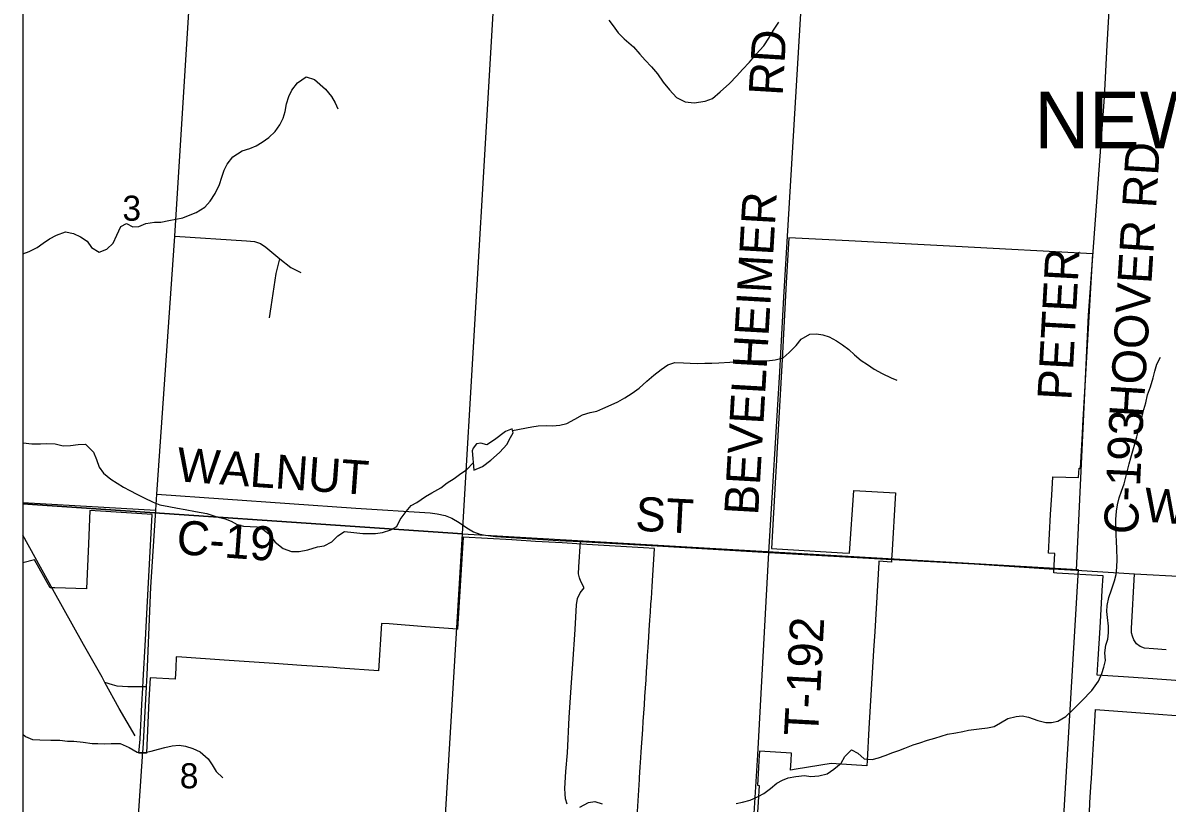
# Model space of a CAD drawing. Extents: x 0 to 91.3, y -0.7 to 22.
# Drawn here: x 2.1 to 4.012, y 19.336 to 20.64 of the extents above; entities that cross this region are included whole.
import ezdxf

# ---------------------------------------------------------------- set-up
doc = ezdxf.new("R2010")
doc.units = 0
for name, color, linetype in [('GM_X_City_Street', 7, 'Continuous'), ('GM_X_Corporation', 7, 'Continuous'), ('GM_X_Corporation_Text', 7, 'Continuous'), ('GM_X_County_Road', 7, 'Continuous'), ('GM_X_County_Road_Text', 7, 'Continuous'), ('GM_X_Minor_Lake', 7, 'Continuous'), ('GM_X_Minor_River', 7, 'Continuous'), ('GM_X_Section_Text', 7, 'Continuous'), ('GM_X_State_Route', 7, 'Continuous'), ('GM_X_Township_Road', 7, 'Continuous'), ('GM_X_Township_Road_Text', 7, 'Continuous'), ('SH_Data', 7, 'Continuous')]:
    doc.layers.add(name, color=color, linetype=linetype)

msp = doc.modelspace()

# ---------------------------------------------------------------- linework, layer by layer
at = {"layer": 'GM_X_City_Street'}
for points in [[(3.0097, 19.3345), (3.0069, 19.3435), (3.0061, 19.352), (3.0058, 19.361), (3.0075, 19.3891), (3.0099, 19.4203), (3.0127, 19.4793), (3.017, 19.5378), (3.0192, 19.5685), (3.0231, 19.6264), (3.0252, 19.6677), (3.0266, 19.6784), (3.031, 19.6876), (3.0381, 19.6961), (3.0324, 19.7065), (3.0299, 19.7128), (3.0285, 19.7196), (3.0288, 19.7311), (3.0318, 19.7734)], [(2.2876, 19.4488), (2.261, 19.4947), (2.2372, 19.5381)]]:
    msp.add_lwpolyline(points, dxfattribs=at)
at = {"layer": 'GM_X_Corporation'}
for points in [[(4.7833, 18.1361), (4.8242, 18.6326), (4.8251, 18.6439), (4.8263, 18.646), (4.8271, 18.6491), (4.8277, 18.656), (4.8336, 18.7529), (4.834, 18.7568), (4.8352, 18.7619), (4.9205, 20.3667), (4.9376, 20.6305), (4.9448, 20.7239), (3.9216, 20.777), (3.4006, 20.8086), (3.3908, 20.8093), (3.2209, 20.8181), (3.0994, 20.8263), (2.3878, 20.8673), (2.1, 20.8844), (2.1, 14.1)], [(4.7833, 18.1361), (4.8242, 18.6326), (4.8251, 18.6439), (4.8263, 18.646), (4.8271, 18.6491), (4.8277, 18.656), (4.8336, 18.7529), (4.834, 18.7568), (4.8352, 18.7619), (4.9205, 20.3667), (4.9376, 20.6305), (4.9448, 20.7239), (3.9216, 20.777), (3.4006, 20.8086), (3.3908, 20.8093), (3.2209, 20.8181), (3.0994, 20.8263), (2.3878, 20.8673), (2.1, 20.8844), (2.1, 15.7138)], [(4.0647, 19.5386), (3.9805, 19.5443), (3.9392, 19.5471), (3.8954, 19.55), (3.897, 19.5771), (3.9, 19.629), (3.9012, 19.6499), (3.9024, 19.6706), (3.9035, 19.6914), (3.9049, 19.716), (3.828, 19.7208), (3.8226, 19.7211), (3.8227, 19.723), (3.8234, 19.7341), (3.8246, 19.7535), (3.8138, 19.7542), (3.8156, 19.7864), (3.8174, 19.8185), (3.8193, 19.8507), (3.821, 19.8816), (3.843, 19.8809), (3.8642, 19.8803), (3.8651, 19.896), (3.8671, 19.8958), (3.8705, 19.9542), (3.8713, 19.9672), (3.8752, 20.0338), (3.8881, 20.2539), (3.659, 20.2662), (3.5957, 20.2696), (3.48, 20.2758), (3.3799, 20.2811), (3.3757, 20.2054), (3.3686, 20.0776), (3.3599, 19.9208), (3.3593, 19.9095), (3.3577, 19.8809), (3.3511, 19.7616), (3.4698, 19.7547), (3.4811, 19.754), (3.4883, 19.8586), (3.5582, 19.8547), (3.552, 19.7499), (3.5517, 19.7449), (3.5514, 19.7392), (3.5305, 19.7404), (3.5304, 19.7385), (3.5235, 19.6232), (3.5216, 19.5915), (3.5138, 19.4611), (3.5106, 19.4074), (3.5101, 19.3988), (3.4509, 19.4026), (3.3924, 19.3931), (3.3829, 19.3916), (3.3838, 19.4074), (3.3845, 19.4196), (3.3307, 19.4231), (3.3298, 19.4074), (3.329, 19.3951), (3.3273, 19.3663), (3.3301, 19.3657), (3.3285, 19.3382), (3.326, 19.2957)], [(3.1257, 19.3044), (3.1304, 19.3758), (3.1306, 19.3792), (3.1317, 19.3962), (3.1328, 19.4123), (3.1334, 19.4223), (3.1358, 19.4592), (3.1367, 19.4726), (3.1376, 19.4866), (3.1385, 19.5006), (3.1395, 19.5146), (3.1404, 19.5286), (3.1413, 19.5426), (3.1422, 19.5565), (3.1431, 19.5703), (3.144, 19.5836), (3.1444, 19.5894), (3.1448, 19.5968), (3.1459, 19.6138), (3.1467, 19.6251), (3.1478, 19.6422), (3.1487, 19.6554), (3.1495, 19.6686), (3.1502, 19.6784), (3.1515, 19.6981), (3.1521, 19.7076), (3.1557, 19.7619), (3.1368, 19.763), (3.1085, 19.7647), (3.0422, 19.7686), (3.001, 19.7711), (2.9568, 19.7737), (2.9171, 19.776), (2.8358, 19.7809), (2.826, 19.627), (2.7728, 19.6311), (2.7121, 19.6358), (2.6995, 19.6367), (2.6945, 19.5576), (2.6303, 19.562), (2.6189, 19.5628), (2.5655, 19.5665), (2.5198, 19.5696), (2.4363, 19.5754), (2.3657, 19.5803), (2.3563, 19.5809), (2.3553, 19.5619), (2.3544, 19.5432), (2.3125, 19.5459), (2.3106, 19.5083), (2.3063, 19.4196), (2.2938, 19.4198), (2.2957, 19.4434), (2.2988, 19.5013), (2.3003, 19.529), (2.301, 19.5413), (2.3047, 19.6089), (2.3076, 19.6632), (2.316, 19.8187), (2.2386, 19.8236), (2.212, 19.8253), (2.2096, 19.7696), (2.2065, 19.6946), (2.1536, 19.6963), (2.1454, 19.6963), (2.1193, 19.7428), (2.1, 19.7378), (2.1, 15.7194)], [(3.8821, 19.3203), (3.8831, 19.3373), (3.8842, 19.3547), (3.8852, 19.3717), (3.8855, 19.3758), (3.8862, 19.3888), (3.8871, 19.4049), (3.8873, 19.4074), (3.8905, 19.4635), (3.8922, 19.4929), (4.1325, 19.475)]]:
    msp.add_lwpolyline(points, dxfattribs=at)
for points in [[(2.1, 20.8816), (2.1, 19.8366), (2.8346, 19.7864), (2.8964, 20.8363), (2.3899, 20.8648)], [(2.1, 19.8366), (2.1, 18.819), (2.7736, 18.7721), (2.8346, 19.7864)], [(2.8346, 19.7864), (3.8634, 19.7265), (3.8019, 18.6958), (2.7736, 18.7721)]]:
    msp.add_lwpolyline(points, close=True, dxfattribs=at)
at = {"layer": 'GM_X_County_Road'}
for p, q in [((2.322, 19.8256), (2.3236, 19.8526)), ((2.1, 19.8389), (2.322, 19.8256)), ((3.5448, 19.744), (3.5645, 19.7429))]:
    msp.add_line(p, q, dxfattribs=at)
for points in [[(3.8606, 19.7255), (3.8807, 20.1515), (3.9073, 20.5159), (3.9118, 20.603), (3.9219, 20.7764)], [(2.3236, 19.8526), (2.6561, 19.8291), (2.7803, 19.8212), (2.7925, 19.8199), (2.8054, 19.817), (2.8166, 19.8123), (2.8288, 19.8051), (2.842, 19.7965), (2.8529, 19.7899), (2.8637, 19.7856), (2.873, 19.784), (2.8898, 19.7817), (2.9949, 19.7754), (3.0318, 19.7734), (3.1598, 19.7665), (3.3467, 19.7553), (3.4746, 19.7481), (3.5428, 19.7441), (3.5448, 19.744)], [(2.1503, 19.6934), (2.1412, 19.7097), (2.1, 19.7843)], [(3.5645, 19.7429), (3.6895, 19.7359), (3.8148, 19.7279), (3.8207, 19.7276)], [(3.8207, 19.7276), (3.8606, 19.7255), (3.9577, 19.7193), (4.1234, 19.7106), (4.3298, 19.697)], [(2.2323, 19.5468), (2.2014, 19.6014), (2.1503, 19.6934)], [(2.3065, 19.5309), (2.2905, 19.5306), (2.2751, 19.5304), (2.2576, 19.532), (2.2495, 19.534), (2.2372, 19.5381), (2.2323, 19.5468)]]:
    msp.add_lwpolyline(points, dxfattribs=at)
at = {"layer": 'GM_X_Minor_Lake'}
for points in [[(2.8538, 19.8929), (2.8679, 19.8989), (2.882, 19.9091), (2.8965, 19.9223), (2.9091, 19.9362), (2.9125, 19.9434), (2.9194, 19.9551), (2.9176, 19.9616), (2.9065, 19.9575), (2.8882, 19.9432), (2.8753, 19.9349), (2.8654, 19.938), (2.8578, 19.9369), (2.8525, 19.9294), (2.8509, 19.9252)], [(2.8509, 19.9252), (2.8538, 19.8929)]]:
    msp.add_lwpolyline(points, dxfattribs=at)
at = {"layer": 'GM_X_Minor_River'}
for points in [[(3.0793, 20.6448), (3.0861, 20.6353), (3.0948, 20.6235), (3.1049, 20.6136), (3.1204, 20.6002), (3.131, 20.5876), (3.14, 20.5777), (3.1502, 20.5666), (3.1607, 20.5548), (3.1701, 20.5411), (3.1807, 20.5281), (3.192, 20.5155), (3.2068, 20.5079), (3.2215, 20.5062), (3.2402, 20.5092), (3.2523, 20.5137), (3.2653, 20.5246), (3.2806, 20.5385), (3.2932, 20.5517), (3.3024, 20.5619), (3.3142, 20.5744), (3.3253, 20.5876), (3.3383, 20.6019), (3.3467, 20.6144), (3.3544, 20.628), (3.3632, 20.6413)], [(2.3304, 20.3071), (2.3441, 20.3097), (2.3555, 20.3119), (2.3672, 20.3144), (2.3794, 20.3193), (2.3897, 20.3234), (2.4042, 20.3321), (2.4129, 20.3419), (2.4214, 20.3547), (2.4283, 20.3702), (2.4322, 20.382), (2.4364, 20.3941), (2.4414, 20.4039), (2.4506, 20.4164), (2.4666, 20.4262), (2.4791, 20.4299), (2.4898, 20.4348), (2.4997, 20.4408), (2.5111, 20.4487), (2.5218, 20.4585), (2.5291, 20.4694), (2.5352, 20.4808), (2.5383, 20.4918), (2.5407, 20.5046), (2.5446, 20.5171), (2.5492, 20.5277), (2.5591, 20.5398), (2.5736, 20.55), (2.5873, 20.5453), (2.6054, 20.5293), (2.6159, 20.5171), (2.6219, 20.5064), (2.6264, 20.4965)], [(2.1, 20.2541), (2.1107, 20.258), (2.1241, 20.2647), (2.134, 20.2722), (2.1446, 20.279), (2.1564, 20.2854), (2.1713, 20.291), (2.1845, 20.2882), (2.1963, 20.2825), (2.2072, 20.2752), (2.2144, 20.2645), (2.2272, 20.2569), (2.2405, 20.2621), (2.2508, 20.2719), (2.257, 20.2855), (2.2635, 20.2999), (2.2731, 20.3048), (2.2837, 20.299), (2.2935, 20.2997), (2.3057, 20.305), (2.3201, 20.3068), (2.3304, 20.3071)], [(2.9184, 19.9587), (2.9502, 19.9652), (2.9613, 19.9667), (2.9745, 19.9673), (2.9852, 19.9665), (2.9973, 19.968), (3.0087, 19.9709), (3.0224, 19.9777), (3.035, 19.9852), (3.0479, 19.9889), (3.0593, 19.9911), (3.0692, 19.9956), (3.0829, 20.002), (3.0943, 20.0068), (3.1058, 20.0136), (3.1183, 20.0215), (3.1298, 20.0298), (3.1424, 20.0411), (3.1542, 20.0513), (3.1664, 20.0611), (3.1778, 20.0686), (3.1896, 20.0727), (3.2037, 20.0722), (3.215, 20.0714), (3.2276, 20.0709), (3.2397, 20.0712), (3.2511, 20.0712), (3.2629, 20.0719), (3.2811, 20.0729), (3.2917, 20.074), (3.3069, 20.0754), (3.3179, 20.0757), (3.343, 20.0756), (3.357, 20.077), (3.3703, 20.0803), (3.3802, 20.0894), (3.3921, 20.1011), (3.4005, 20.1113), (3.415, 20.1199), (3.426, 20.1202), (3.4366, 20.1187), (3.4472, 20.1152), (3.4593, 20.1087), (3.4695, 20.1021), (3.4801, 20.0945), (3.4899, 20.0853), (3.5009, 20.0761), (3.5114, 20.0693), (3.5224, 20.0616), (3.536, 20.0539), (3.5508, 20.047), (3.5606, 20.0432)], [(3.5537, 19.4208), (3.5636, 19.4242), (3.5739, 19.4279), (3.5879, 19.4335), (3.599, 19.4373), (3.6115, 19.4418), (3.6241, 19.4447), (3.6343, 19.4481), (3.645, 19.4514), (3.6587, 19.4536), (3.6704, 19.4558), (3.6799, 19.458), (3.6982, 19.4606), (3.7118, 19.462), (3.7232, 19.4646), (3.7335, 19.4703), (3.7461, 19.4778), (3.7598, 19.4811), (3.7697, 19.4822), (3.7806, 19.4798), (3.7958, 19.4744), (3.8091, 19.4713), (3.8189, 19.4709), (3.8292, 19.4735), (3.8425, 19.481), (3.8551, 19.4927), (3.8696, 19.507), (3.8861, 19.5244), (3.8975, 19.5399), (3.9029, 19.5527), (3.9064, 19.5637), (3.9088, 19.5747), (3.9077, 19.5872), (3.9097, 19.6005), (3.9132, 19.6104), (3.914, 19.6206), (3.9141, 19.632), (3.9126, 19.6464), (3.9115, 19.6563), (3.9116, 19.6665), (3.9144, 19.6798), (3.919, 19.6927), (3.924, 19.7078), (3.9267, 19.7184), (3.928, 19.7306), (3.9284, 19.7435), (3.9278, 19.7613), (3.9275, 19.7742), (3.9268, 19.7841), (3.9265, 19.7966), (3.9265, 19.8103), (3.9274, 19.8239), (3.929, 19.8345), (3.9321, 19.8463), (3.936, 19.8573), (3.9402, 19.8701), (3.9433, 19.8811), (3.9488, 19.9031), (3.9515, 19.913), (3.955, 19.9251), (3.9588, 19.9383), (3.9612, 19.9486), (3.9643, 19.9596), (3.9678, 19.9736), (3.9705, 19.9831), (3.9729, 19.994), (3.9763, 20.0054), (3.9791, 20.0183), (3.9845, 20.0319), (3.9887, 20.0467), (3.9915, 20.0581), (3.9946, 20.0698), (4.0007, 20.0812)], [(2.1, 19.9382), (2.1004, 19.9381), (2.1148, 19.9369), (2.1296, 19.9368)], [(2.1296, 19.9368), (2.1402, 19.9371), (2.1539, 19.9366), (2.1671, 19.9331), (2.1797, 19.9338), (2.1926, 19.9357), (2.2047, 19.936), (2.2179, 19.923), (2.2228, 19.9104), (2.2273, 19.8975), (2.2348, 19.8876), (2.2469, 19.8776), (2.2575, 19.8707), (2.2684, 19.8642), (2.2786, 19.8585), (2.2904, 19.8523), (2.3028, 19.8466), (2.3176, 19.8393), (2.329, 19.8346), (2.3441, 19.8319), (2.3585, 19.8291), (2.371, 19.8268), (2.3885, 19.8236), (2.3979, 19.8217), (2.4074, 19.8201), (2.4241, 19.8147), (2.4381, 19.8112), (2.4483, 19.8073), (2.4582, 19.8016), (2.4684, 19.7992), (2.4798, 19.7988), (2.4908, 19.798), (2.501, 19.7941), (2.5112, 19.7861), (2.5217, 19.7724), (2.5349, 19.7616), (2.549, 19.757), (2.5615, 19.7566), (2.5759, 19.7595), (2.5923, 19.7647), (2.6037, 19.7665), (2.6162, 19.7729), (2.6265, 19.7827), (2.6376, 19.7902), (2.6531, 19.7886), (2.6679, 19.787), (2.6789, 19.7866), (2.6892, 19.7869), (2.7009, 19.7883), (2.7146, 19.7928), (2.7249, 19.7988), (2.7307, 19.8102), (2.7403, 19.8234), (2.7487, 19.8336), (2.7582, 19.8385), (2.773, 19.8486), (2.7833, 19.8546), (2.7982, 19.8633), (2.8092, 19.8716), (2.8207, 19.8787), (2.8317, 19.887), (2.8413, 19.893), (2.8527, 19.9055)], [(2.1, 19.4514), (2.1045, 19.4478), (2.1163, 19.4428), (2.1284, 19.4419), (2.1466, 19.4418), (2.1618, 19.4414), (2.1743, 19.4401), (2.1849, 19.4397), (2.2009, 19.4381), (2.216, 19.4361), (2.2255, 19.4357), (2.2358, 19.4352), (2.2475, 19.4359), (2.2623, 19.4358), (2.2775, 19.4293), (2.2907, 19.4216), (2.304, 19.4211), (2.3146, 19.4234), (2.3268, 19.4263), (2.3371, 19.4293), (2.3492, 19.4319), (2.361, 19.4333), (2.3716, 19.4317), (2.3841, 19.4275), (2.3962, 19.4221), (2.4094, 19.4103), (2.4162, 19.4003), (2.4229, 19.3893), (2.4343, 19.3786)], [(3.2921, 19.3359), (3.3023, 19.3377), (3.3152, 19.3414), (3.3286, 19.3474), (3.3381, 19.3527), (3.3495, 19.361), (3.3598, 19.3696), (3.3693, 19.3749), (3.3789, 19.3786), (3.3918, 19.3808), (3.4062, 19.3823), (3.4168, 19.3811), (3.4301, 19.3817), (3.4438, 19.3851), (3.4549, 19.393), (3.4671, 19.4031), (3.4732, 19.4145), (3.4847, 19.4254), (3.4952, 19.4197), (3.5058, 19.4105), (3.5191, 19.4093), (3.5297, 19.4119), (3.5411, 19.416), (3.5537, 19.4208)], [(3.0309, 19.3295), (3.0454, 19.3373), (3.0556, 19.3392), (3.0681, 19.3349)]]:
    msp.add_lwpolyline(points, dxfattribs=at)
at = {"layer": 'GM_X_State_Route'}
msp.add_line((2.322, 19.8256), (2.3236, 19.8526), dxfattribs=at)
for points in [[(2.3236, 19.8526), (2.354, 20.2835), (2.3719, 20.5693), (2.3803, 20.7028), (2.3881, 20.8667)], [(2.3074, 19.5506), (2.3138, 19.6973), (2.322, 19.8256)], [(2.3, 19.4144), (2.3001, 19.4165), (2.3009, 19.4272), (2.3065, 19.5309), (2.3074, 19.5506)], [(2.2599, 18.8035), (2.2625, 18.8564), (2.2672, 18.9235), (2.2866, 19.2202), (2.292, 19.2987), (2.3, 19.4144)]]:
    msp.add_lwpolyline(points, dxfattribs=at)
at = {"layer": 'GM_X_Township_Road'}
for points in [[(3.3467, 19.7553), (3.3647, 20.0567), (3.3715, 20.1817), (3.377, 20.2742), (3.4081, 20.7959), (3.4063, 20.8026), (3.4008, 20.8081)], [(2.354, 20.2835), (2.4735, 20.2759), (2.4871, 20.2746), (2.4973, 20.2712), (2.5062, 20.2652), (2.5296, 20.2456), (2.5479, 20.2312), (2.5577, 20.2261), (2.5645, 20.2231)], [(2.5122, 20.147), (2.5147, 20.1653), (2.5232, 20.2214), (2.5296, 20.2456)], [(3.3193, 19.2743), (3.3279, 19.4173), (3.3467, 19.7553)], [(4.0107, 19.5925), (3.9891, 19.594), (3.9744, 19.5951), (3.9667, 19.5983), (3.9609, 19.6026), (3.9566, 19.6089), (3.9543, 19.6153), (3.9526, 19.6208), (3.9526, 19.6282), (3.9577, 19.7193)]]:
    msp.add_lwpolyline(points, dxfattribs=at)
at = {"layer": 'SH_Data'}
msp.add_line((2.1, 20.9), (2.1, 14.1), dxfattribs=at)

# ---------------------------------------------------------------- texts
at = {"layer": 'GM_X_Corporation_Text'}
msp.add_text('NEW ALBANY', height=0.0947, rotation=0, dxfattribs=at).set_placement((3.7903, 20.4305))
at = {"layer": 'GM_X_County_Road_Text'}
for s, rotation, p in [('HOOVER RD', 86.4746, (3.972, 19.9797)), ('PETER', 86.8434, (3.8519, 20.0086)), ('C-193', 87.2469, (3.9628, 19.7846)), ('WALNUT', 355.8696, (2.3559, 19.8742)), ('ST', 357.05, (3.1225, 19.7917)), ('WALNUT', 356.0379, (3.9721, 19.8068)), ('C-19', 355.8663, (2.3555, 19.7526))]:
    msp.add_text(s, height=0.05682, rotation=rotation, dxfattribs=at).set_placement(p)
at = {"layer": 'GM_X_Section_Text'}
for s, p in [('3', (2.2663, 20.3094)), ('8', (2.3622, 19.3611))]:
    msp.add_text(s, height=0.0419, rotation=0, dxfattribs=at).set_placement(p)
at = {"layer": 'GM_X_Township_Road_Text'}
for s, height, rotation, p in [('RD', 0.05682, 86.5467, (3.3694, 20.5174)), ('BEVELHEIMER', 0.056818, 86.6909, (3.3286, 19.8165)), ('T-192', 0.05682, 86.913, (3.4285, 19.4474))]:
    msp.add_text(s, height=height, rotation=rotation, dxfattribs=at).set_placement(p)

doc.saveas('drawing.dxf')
